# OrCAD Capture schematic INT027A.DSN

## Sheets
1 00_Block_Revision_Note: title: 3220UFP-DGLEVM INT027; rev: A.0; company: Texas Instruments, CIS/ICP
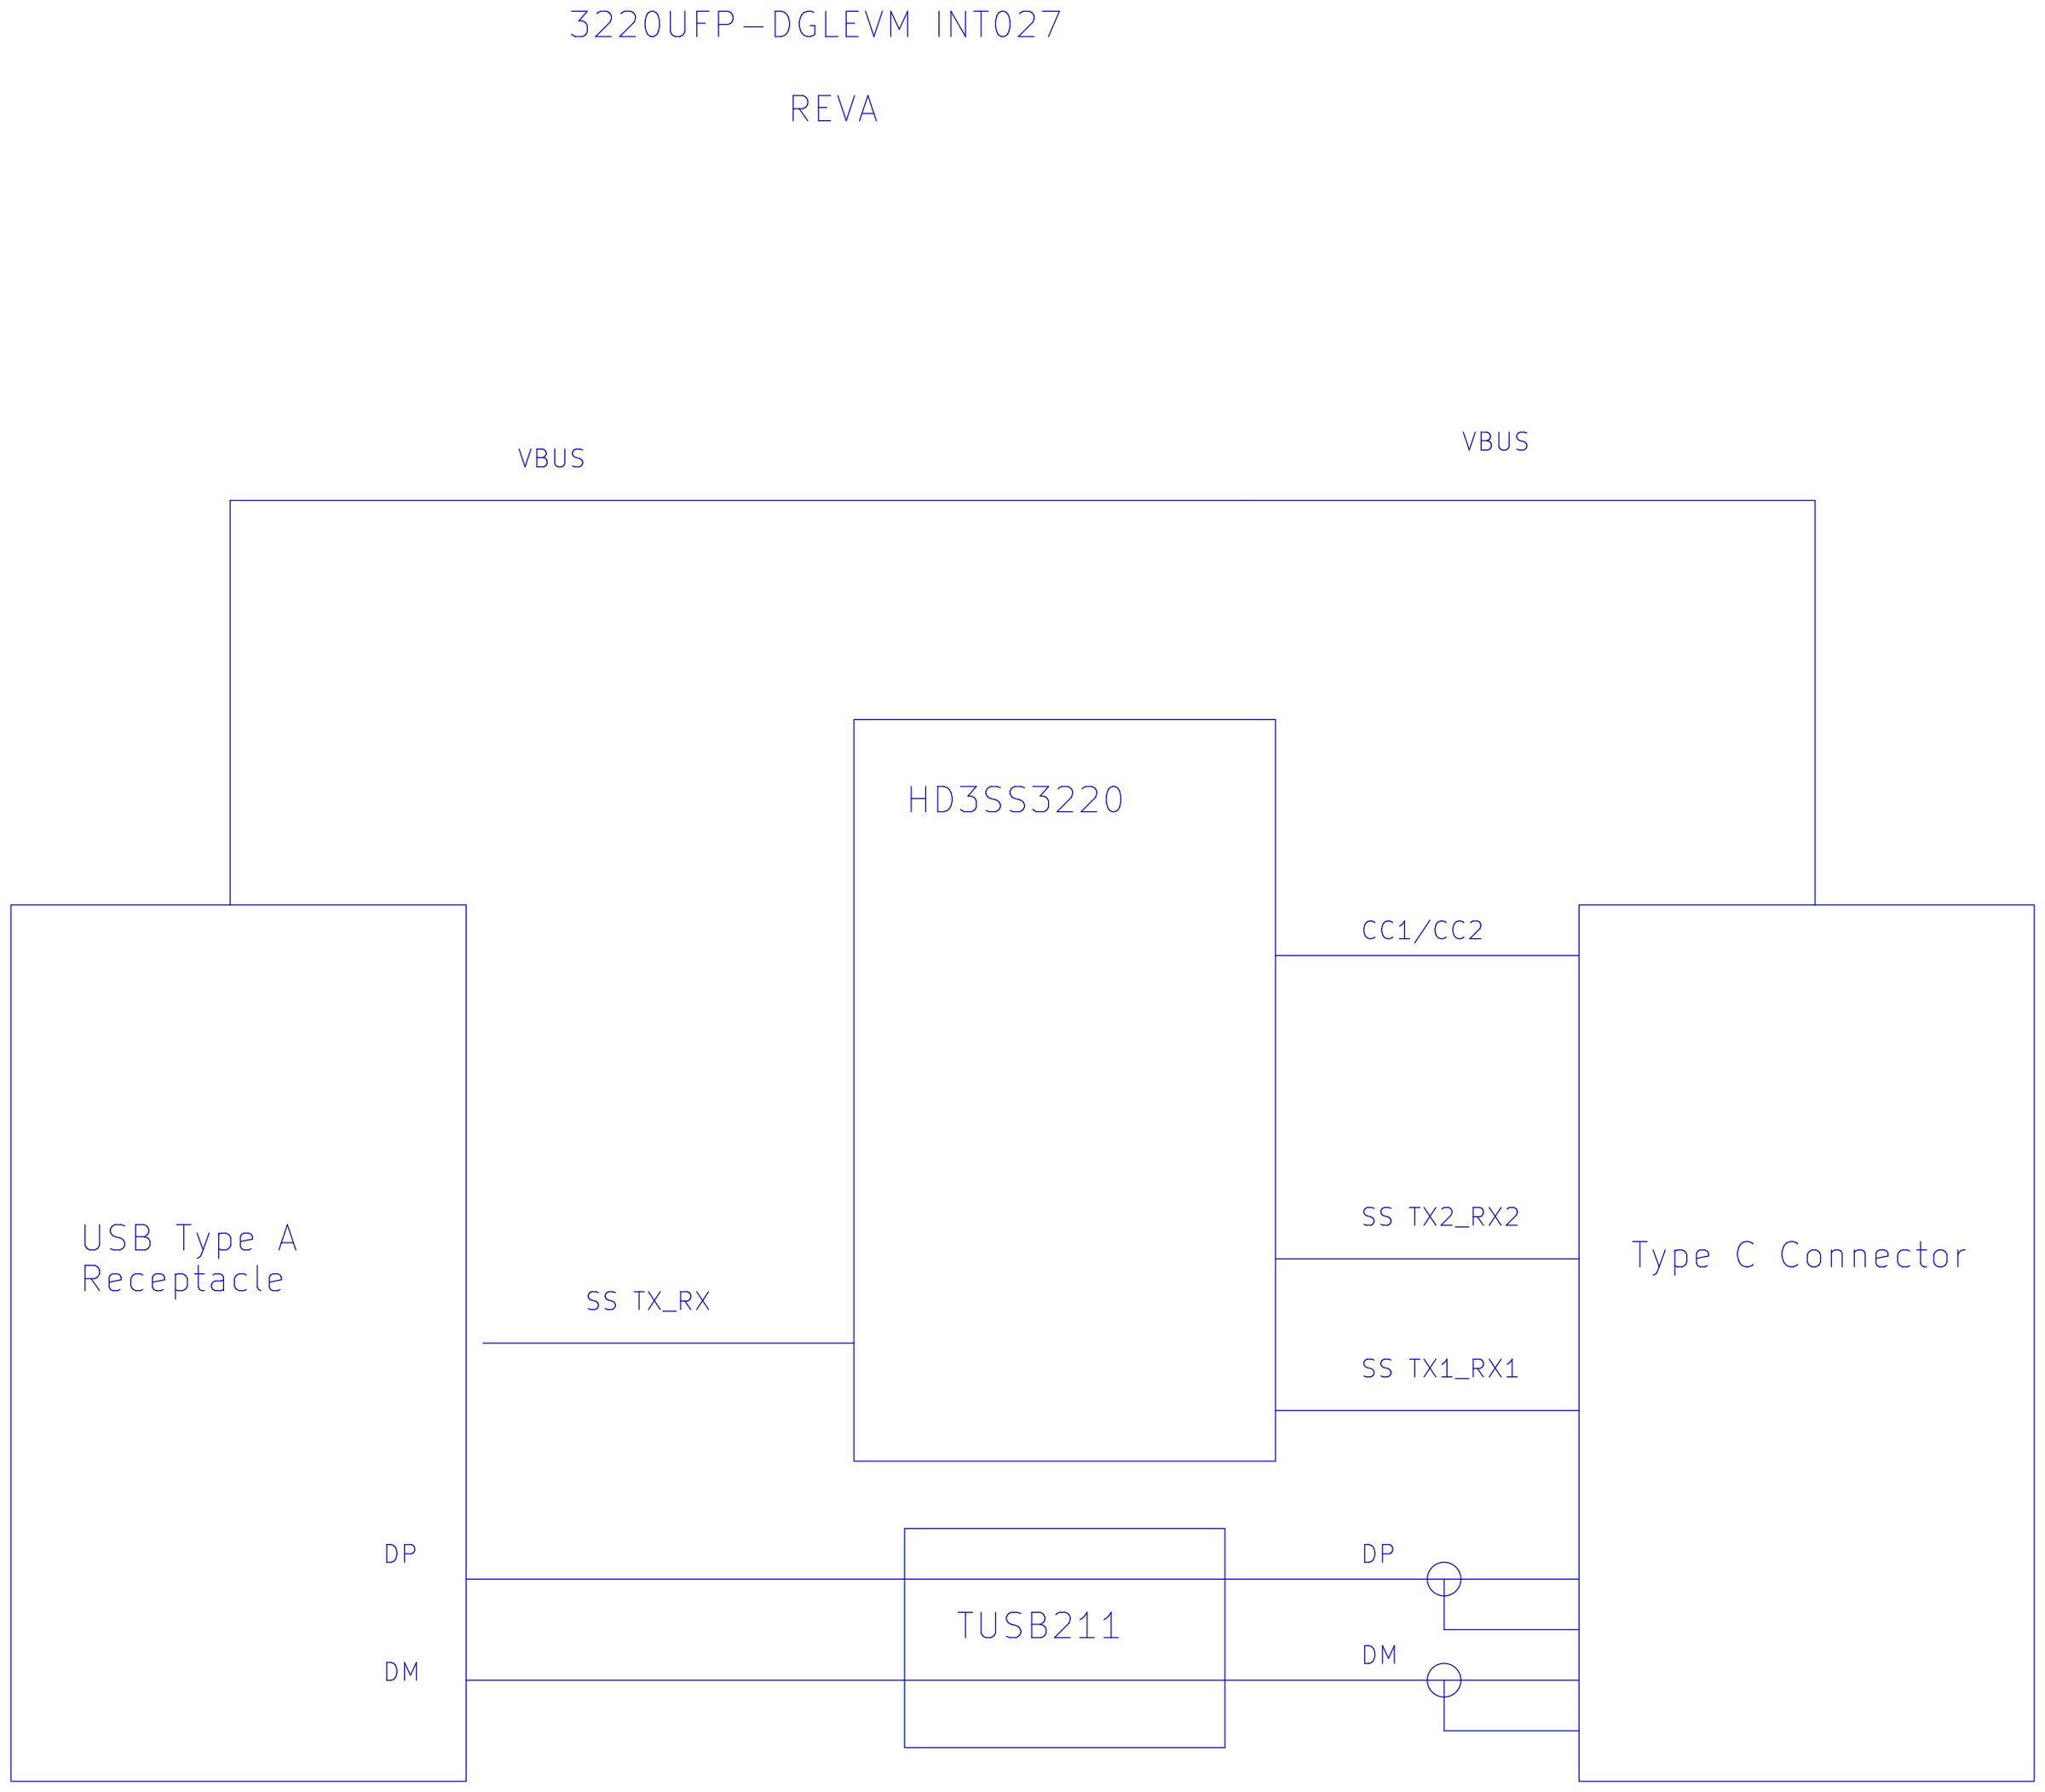
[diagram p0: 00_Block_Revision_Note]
2 PAGE1_HD3SS3220: size C; title: 3220UFP-DGLEVM INT027: TUSB3220
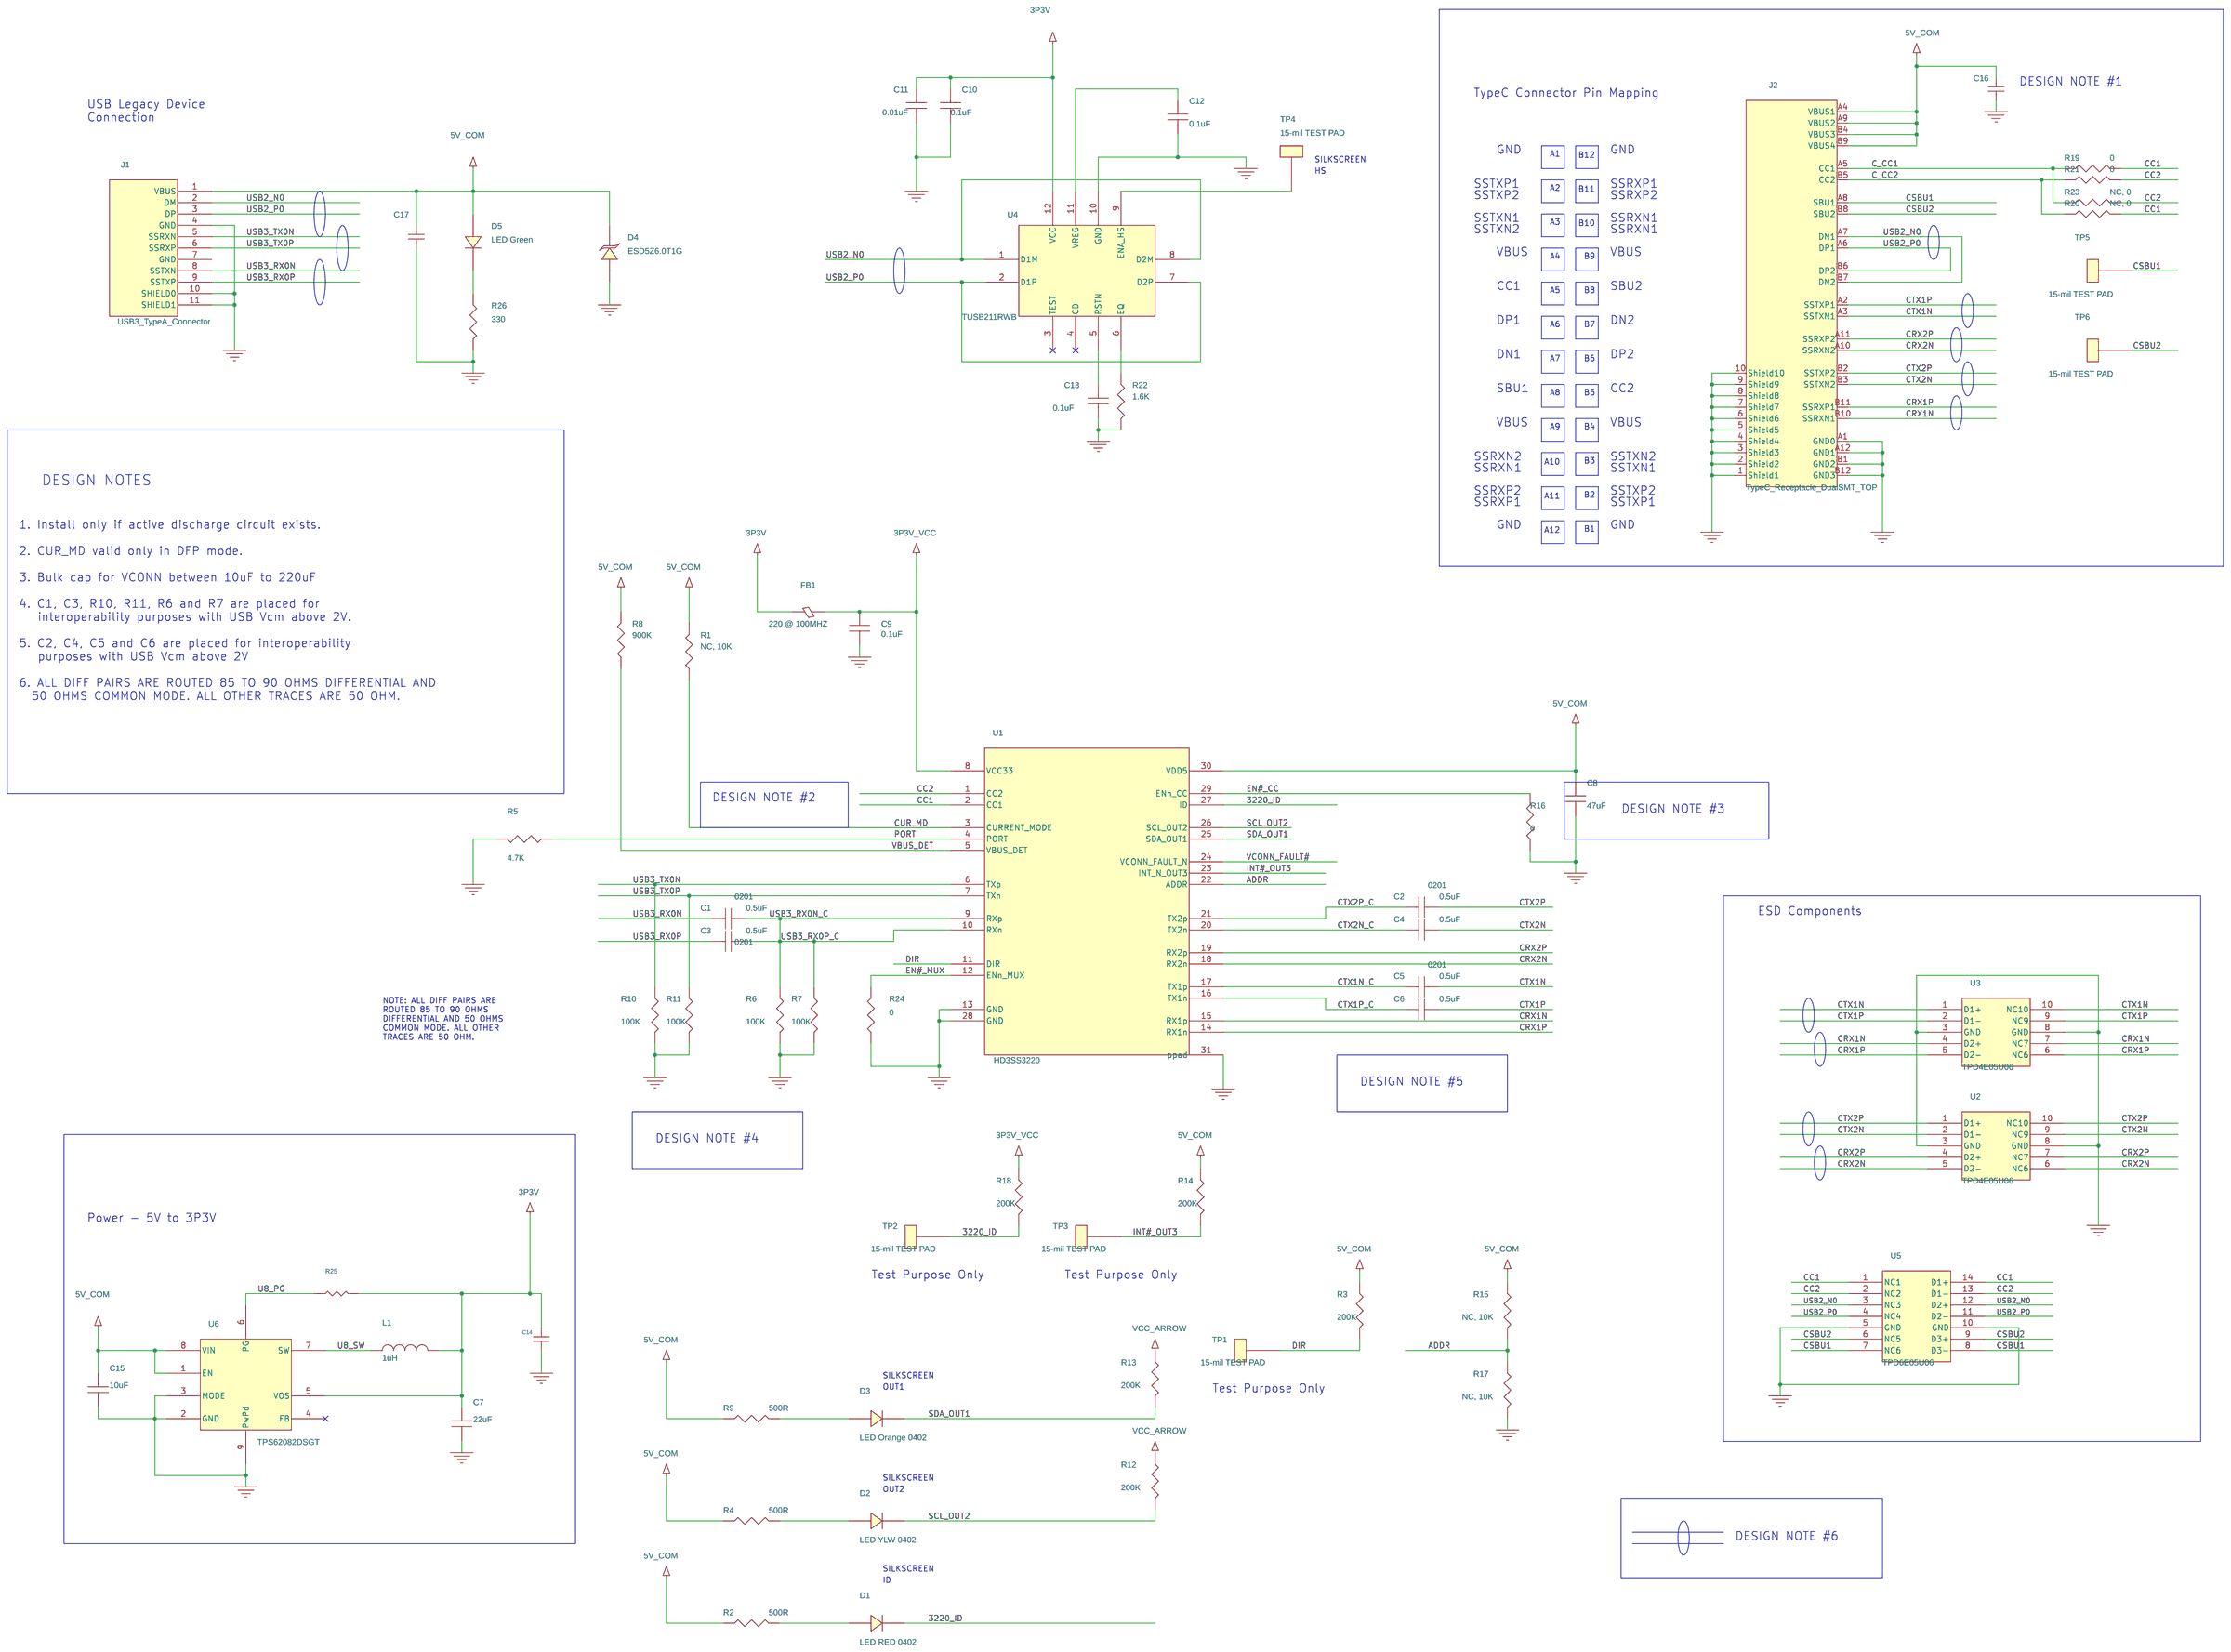
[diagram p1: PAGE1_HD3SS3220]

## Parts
C1  0.5uF  [0201]
C2  0.5uF  [0201]
C3  0.5uF  [0201]
C4  0.5uF  [0201]
C5  0.5uF  [0201]
C6  0.5uF  [0201]
C7  22uF  [0805]
C8  47uF  [0805]
C9  0.1uF  [0402]
C10  0.1uF  [0402]
C11  0.01uF  [0402]
C12  0.1uF  [0402]
C13  0.1uF  [0402]
C14  10uF  [0805]
C15  10uF  [0805]
C16  NC, 10uF  [0603]
C17  10uF  [0805]
D1  LED RED 0402  [LED_0402]
D2  LED YLW 0402  [LED_0402]
D3  LED Orange 0402  [LED_0402]
D4  ESD5Z6.0T1G  [SOD_523]
D5  LED Green  [LED_0402]
FB1  220 @ 100MHZ  [0603]
J1  USB3_TypeA_Connector  [USB3_TYPEA]
J2  TypeC_Receptacle_DualSMT_TOP  [USB_TYPEC_UT1211]
L1  1uH  [IND_NR3015]
R1  NC, 10K  [0402]
R2  500R  [0402]
R3  200K  [0201]
R4  500R  [0402]
R5  4.7K  [0402]
R6  100K  [0201]
R7  100K  [0201]
R8  900K  [0402]
R9  500R  [0402]
R10  100K  [0201]
R11  100K  [0201]
R12  200K  [0201]
R13  200K  [0201]
R14  200K  [0201]
R15  NC, 10K  [0201]
R16  0  [0402]
R17  NC, 10K  [0201]
R18  200K  [0201]
R19  0  [0402]
R20  NC, 0  [0402]
R21  0  [0402]
R22  1.6K  [0402]
R23  NC, 0  [0402]
R24  0  [0402]
R25  178K  [0402]
R26  330  [0402]
TP1  15-mil TEST PAD  [15_mil_Round_Probe_Point]
TP2  15-mil TEST PAD  [15_mil_Round_Probe_Point]
TP3  15-mil TEST PAD  [15_mil_Round_Probe_Point]
TP4  15-mil TEST PAD  [15_mil_Round_Probe_Point]
TP5  15-mil TEST PAD  [15_mil_Round_Probe_Point]
TP6  15-mil TEST PAD  [15_mil_Round_Probe_Point]
U1  HD3SS3220  [RNH_QFN-30]
U2  TPD4E05U06  [DQA]
U3  TPD4E05U06  [DQA]
U4  TUSB211RWB  [RWB]
U5  TPD6E05U06  [RVZ]
U6  TPS62082DSGT  [dsg]

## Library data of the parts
C1-C7 C15 = CAP_NP: 6.3V Capacitor
C8 = CAP_NP: 10V
C9 = CAP_NP
C10-C13 = cc0402
C14 = CAP: 6.3V Capacitor; $SEC: 1; ATIPartNo: 4210010600G; CDS_LIB: capacitor; DRAWING: @LIGHTNING_BOLT_NB_LIB.NOTE_BOOK(SCH_1):PAGE1; PHYS_PAGE: 1; ROT: 0; TOLERANCE: 10%; VER: 1; VOLTAGE: 6.3V; XY: (-9500,3550)
C16 C17 = CAP: 10V Capacitor; $SEC: 1; ATIPartNo: 4212010600G; CDS_LIB: capacitor; DRAWING: @LIGHTNING_BOLT_NB_LIB.NOTE_BOOK(SCH_1):PAGE2; GroupName: COMMON; PHYS_PAGE: 2; REFD_LOCKED: TRUE; ROT: 1; TOLERANCE: 10%; VER: 1; VOLTAGE: 10V; XY: (-5750,6050)
D1 = DIODE_0: Orange LED; Digi-Key Part Number: 67-1878-1-ND; Manuf: Lumex; Manuf PN: SML-LX0402SYC-TR; Manufacturer: Lumex; Manufacturer Part Number: SML-LX0402SIC-TR; Manufacturer's Part Number: SML-LX0402SIC-TR
D2 = DIODE_0: Orange LED; Digi-Key Part Number: 67-1880-1-ND; Manuf: Lumex; Manuf PN: SML-LX0402SYC-TR; Manufacturer: Lumex; Manufacturer Part Number: SML-LX0402SYC-TR; Manufacturer's Part Number: SML-LX0402SYC-TR
D3 = DIODE_0: Orange LED; Digi-Key Part Number: 67-1879-1-ND; Manuf: Lumex; Manuf PN: SML-LX0402SOC-TR; Manufacturer: Lumex; Manufacturer Part Number: SML-LX0402SOC-TR; Manufacturer's Part Number: SML-LX0402SOC-TR
D4 = DIODE_TAZ: TVS Diode; Digi-Key Part Number: ESD5Z6.0T1GOSCT-ND; Manufacturer: ON Semi
D5 = DIODE_0: Green LED; Digi-Key Part Number: 67-1881-1-ND; Manuf: Lumex; Manuf PN: SML-LX0402SUGC-TR; Manufacturer: Lumex; Manufacturer Part Number: SML-LX0402SUGC-TR; Manufacturer's Part Number: SML-LX0402SUGC-TR
FB1 = FERRITE_BEAD: FBEAD 1000@100MHz; Device: BEAD1806; Digi-Key Part Number: 490-3992-1-ND; MFC: MuRata; Manuf: MuRata; Manuf PN: BLM18EG221SN1D; Manufacturer: MuRata; Manufacturer Part Number: BLM18EG221SN1D; Manufacturer's Part Number: BLM18EG221SN1D; Part Number: BLM18EG221SN1D; Part#: BLM18EG221SN1D
J1 = USB3_TYPEA_CONNECTOR: DigiKey Part Number: GSB311131HR-ND; Manufacturer: Amphenol; Manufacturer Part Number: GSB311131HR
J2 = USBTypeC_Receptacle_TOPMount_0
L1 = INDUCTOR: Inductor; CDS_LIB: Inductor; Digi-Key Part Number: 587-1647-1-ND; Manuf: Taiyo Yuden; Manuf PN: NR3015T1R0N; Manufacturer: Taiyo Yuden; Manufacturer Part Number: NR3015T1R0N; Manufacturer's Part Number: NR3015T1R0N
R1 R5 R8 = RESISTOR
R2 R4 R9 R26 = R: Resistor; Tolerance: 5%
R3 R6 R7 R10-R15 R17 R18 = R_2: Resistor; Manuf: TBD; Manuf PN: TBD; Tolerance: 5%
R16 R19-R21 R23 R24 = R: Resistor
R22 = r0402
R25 = RES: Resistor; $SEC: 1; CDS_LIB: resistor; DRAWING: @LIGHTNING_BOLT_NB_LIB.NOTE_BOOK(SCH_1):PAGE2; PHYS_PAGE: 2; ROT: 0; TOLERANCE: 5%; VER: 1; WATTAGE: 1/16W; XY: (-6100,4550)
TP1-TP6 = TEST_POINT: 15 mil Round Pad
U1 = HD3SS3220_0
U2 U3 = TPD4E05U06
U4 = TUSB211RWB
U5 = TPD6E05U06
U6 = TPS62082_0: DC/DC Converter; Digi-Key Part Number: 296-29647-1-ND; Manuf: Texas Instruments; Manufacturer: Texas Instruments

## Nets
5V_COM: C8.1 C15.1 C16.2(B) C17.2(B) D4.1(CATHODE) D5.2(A) J1.1(VBUS) J2.A4(VBUS1) J2.A9(VBUS2) J2.B4(VBUS3) J2.B9(VBUS4) R1.2 R2.1 R3.1 R4.1 R8.2 R9.1 R12.1 R13.1 R14.1 R15.1 U1.30(VDD5) U6.1(EN) U6.8(VIN)
GND: C7.2 C8.2 C9.2 C10.2 C11.2 C12.2 C13.2 C14.2(B) C15.2 C16.1(A) C17.1(A) D4.2(ANODE) J1.4(GND) J1.7(GND) J1.10(SHIELD0) J1.11(SHIELD1) J2.1(Shield1) J2.2(Shield2) J2.3(Shield3) J2.4(Shield4) J2.5(Shield5) J2.6(Shield6) J2.7(Shield7) J2.8(Shield8) J2.9(Shield9) J2.10(Shield10) J2.A1(GND0) J2.A12(GND1) J2.B1(GND2) J2.B12(GND3) R5.2 R6.2 R7.2 R10.2 R11.2 R16.1 R17.2 R22.2 R24.1 R26.2 U1.13(GND) U1.28(GND) U1.31(ppad) U2.3(GND) U2.8(GND) U3.3(GND) U3.8(GND) U4.10(GND) U5.5(GND) U5.10(GND) U6.2(GND) U6.3(MODE) U6.9(PwPd)
VBUS_DET: R8.1 U1.5(VBUS_DET)
3P3V: C7.1 C10.1 C11.1 C14.1(A) FB1.1 L1.2 R25.2(B) U4.12(VCC) U6.5(VOS)
3P3V_VCC: C9.1 FB1.2 R18.1 U1.8(VCC33)
3220_ID: D1.1(K) R18.2 TP2.1 U1.27(ID)
ADDR: R15.2 R17.1 U1.22(ADDR)
C_CC1: J2.A5(CC1) R19.1 R23.1
C_CC2: J2.B5(CC2) R20.1 R21.1
CC1: R19.2 R20.2 U1.2(CC1) U5.1(NC1) U5.14(D1+)
CC2: R21.2 R23.2 U1.1(CC2) U5.2(NC2) U5.13(D1-)
CRX1N: J2.B10(SSRXN1) U1.15(RX1p) U3.4(D2+) U3.7(NC7)
CRX1P: J2.B11(SSRXP1) U1.14(RX1n) U3.5(D2-) U3.6(NC6)
CRX2N: J2.A10(SSRXN2) U1.18(RX2n) U2.5(D2-) U2.6(NC6)
CRX2P: J2.A11(SSRXP2) U1.19(RX2p) U2.4(D2+) U2.7(NC7)
CSBU1: J2.A8(SBU1) TP5.1 U5.7(NC6) U5.8(D3-)
CSBU2: J2.B8(SBU2) TP6.1 U5.6(NC5) U5.9(D3+)
CTX1N: C5.2 J2.A3(SSTXN1) U3.1(D1+) U3.10(NC10)
CTX1N_C: C5.1 U1.17(TX1p)
CTX1P: C6.2 J2.A2(SSTXP1) U3.2(D1-) U3.9(NC9)
CTX1P_C: C6.1 U1.16(TX1n)
CTX2N: C4.2 J2.B3(SSTXN2) U2.2(D1-) U2.9(NC9)
CTX2N_C: C4.1 U1.20(TX2n)
CTX2P: C2.2 J2.B2(SSTXP2) U2.1(D1+) U2.10(NC10)
CTX2P_C: C2.1 U1.21(TX2p)
CUR_MD: R1.1 U1.3(CURRENT_MODE)
DIR: R3.2 TP1.1 U1.11(DIR)
EN#_CC: R16.2 U1.29(ENn_CC)
EN#_MUX: R24.2 U1.12(ENn_MUX)
INT#_OUT3: R14.2 TP3.1 U1.23(INT_N_OUT3)
PORT: R5.1 U1.4(PORT)
SCL_OUT2: D2.1(K) R12.2 U1.26(SCL_OUT2)
SDA_OUT1: D3.1(K) R13.2 U1.25(SDA_OUT1)
U8_PG: R25.1(A) U6.6(PG)
U8_SW: L1.1 U6.7(SW)
USB2_N0: J1.2(DM) J2.A7(DN1) J2.B7(DN2) U4.1(D1M) U4.8(D2M) U5.3(NC3) U5.12(D2+)
USB2_P0: J1.3(DP) J2.A6(DP1) J2.B6(DP2) U4.2(D1P) U4.7(D2P) U5.4(NC4) U5.11(D2-)
USB3_RX0N: C1.1 J1.8(SSTXN)
USB3_RX0N_C: C1.2 R6.1 U1.9(RXp)
USB3_RX0P: C3.1 J1.9(SSTXP)
USB3_RX0P_C: C3.2 R7.1 U1.10(RXn)
USB3_TX0N: J1.5(SSRXN) R10.1 U1.6(TXp)
USB3_TX0P: J1.6(SSRXP) R11.1 U1.7(TXn)
VCONN_FAULT#: U1.24(VCONN_FAULT_N)
N16911818: C12.1 U4.11(VREG)
N16911898: C13.1 U4.5(RSTN)
N16911900: R22.1 U4.6(EQ)
N16922242: TP4.1 U4.9(ENA_HS)
N16960198: D5.1(K) R26.1
N16963575: D3.2(A) R9.2
N16963631: D2.2(A) R4.2
N16967109: D1.2(A) R2.2

Not connected (* = marked no-connect by the designer): U4 3(TEST)* 4(CD)*; U6 4(FB)*

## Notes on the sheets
sheet 1
- 3220UFP-DGLEVM INT027
- REVA
- VBUS
- VBUS
- HD3SS3220
- CC1/CC2
- SS TX2_RX2
- USB Type A
  Receptacle
- Type C Connector
- SS TX_RX
- SS TX1_RX1
- DP
- DP
- TUSB211
- DM
- DM
sheet 2
- DESIGN NOTE #1
- TypeC Connector Pin Mapping
- USB Legacy Device
  Connection
- GND
- GND
- SILKSCREEN
- A1
- B12
- HS
- SSTXP1
- A2
- B11
- SSRXP1
- SSTXP2
- SSRXP2
- SSTXN1
- SSRXN1
- SSTXN2
- A3
- B10
- SSRXN1
- VBUS
- A4
- B9
- VBUS
- CC1
- SBU2
- A5
- B8
- DP1
- A6
- B7
- DN2
- DN1
- DP2
- A7
- B6
- SBU1
- A8
- B5
- CC2
- VBUS
- A9
- B4
- VBUS
- SSRXN2
- SSTXN2
- SSRXN1
- A10
- B3
- SSTXN1
- DESIGN NOTES
- SSRXP1
- SSRXP2
- A11
- B2
- SSTXP1
- SSTXP2
- 1. Install only if active discharge circuit exists.
  2. CUR_MD valid only in DFP mode.
  3. Bulk cap for VCONN between 10uF to 220uF
  4. C1, C3, R10, R11, R6 and R7 are placed for
     interoperability purposes with USB Vcm above 2V.
  5. C2, C4, C5 and C6 are placed for interoperability
     purposes with USB Vcm above 2V
  6. ALL DIFF PAIRS ARE ROUTED 85 TO 90 OHMS DIFFERENTIAL AND
    50 OHMS COMMON MODE. ALL OTHER TRACES ARE 50 OHM.
- GND
- GND
- A12
- B1
- DESIGN NOTE #2
- DESIGN NOTE #3
- ESD Components
- NOTE: ALL DIFF PAIRS ARE
  ROUTED 85 TO 90 OHMS
  DIFFERENTIAL AND 50 OHMS
  COMMON MODE. ALL OTHER
  TRACES ARE 50 OHM.
- DESIGN NOTE #5
- DESIGN NOTE #4
- Power - 5V to 3P3V
- Test Purpose Only
- Test Purpose Only
- SILKSCREEN
- OUT1
- Test Purpose Only
- SILKSCREEN
- OUT2
- DESIGN NOTE #6
- SILKSCREEN
- ID
